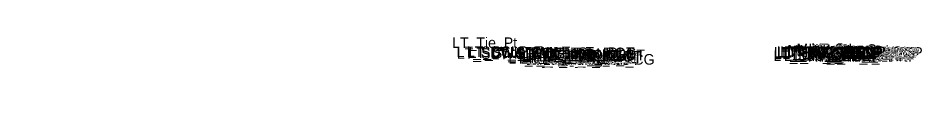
# Model space of a CAD drawing. Extents: x 0 to 4229, y -1 to 9523.
# Drawn here: x 3000 to 3171.5, y 4000 to 4008.4 of the extents above; entities that cross this region are included whole.
import ezdxf

# ---------------------------------------------------------------- set-up
doc = ezdxf.new("R2010")
doc.units = 0
doc.layers.add('Default', color=7, linetype='Continuous')

msp = doc.modelspace()

# ---------------------------------------------------------------- texts
at = {"layer": 'Default'}
for s, height, p in [('LT_Tie_Pt', 2, (3082.37, 4006.27)), ('LT_SDWK_Out_Top', 2, (3083.24, 4004.55)), ('LT_SDWK_Out_Bot', 2, (3083.27, 4004.22)), ('LT_CSLP_Pnt', 2, (3085.17, 4004.58)), ('LT_Sub_Trench_Out_DLT', 2, (3085.49, 4004.38)), ('LT_SDWK_In_Top', 2, (3089.86, 4004.45)), ('LT_SDWK_In_Bot', 2, (3089.89, 4004.12)), ('LT_CG_Top_Face', 2, (3094.76, 4004.34)), ('LT_CG_Top_BOC', 2, (3095.28, 4004.34)), ('LT_CG_Top_Gut', 2, (3095.74, 4003.84)), ('LT_PV2_OEOT', 2, (3099.67, 4003.71)), ('LT_PV1_OEOT', 2, (3100.24, 4003.96)), ('LT_Sub_OEEOP', 2, (3143.35, 4003.81)), ('LT_PV2_OEEOP', 2, (3143.44, 4004.44)), ('LT_PV3_OEEOP', 2, (3143.44, 4004.19)), ('LT_PV1_OEEOP', 2, (3144.01, 4004.56)), ('LT_PV2_IEEOP', 2, (3144.09, 4004.44)), ('LT_PV1_IEEOP', 2, (3144.66, 4004.56)), ('LT_PV2_PGL1', 2, (3145.02, 4004.44)), ('LT_PV3_PGL1', 2, (3145.02, 4004.19)), ('LT_PV2_PGL', 2, (3145.35, 4004.44)), ('LT_PV4_PGL', 2, (3145.35, 4003.81)), ('LT_PV1_PGL', 2, (3145.92, 4004.69)), ('MI_Face In', 2, (3146.04, 4004.85)), ('MI_Bot In', 2, (3147.02, 4004.69)), ('MI_Top In', 2, (3147.75, 4005.1)), ('RT_Sub_OEEOP', 2, (3149.92, 4003.68)), ('RT_PV2_OEEOP', 2, (3150.01, 4004.3)), ('RT_PV3_OEEOP', 2, (3150.01, 4004.05)), ('MI_Crown', 2, (3150.51, 4005.15)), ('RT_PV1_OEEOP', 2, (3150.58, 4004.43)), ('RT_PV2_IEEOP', 2, (3150.66, 4004.3)), ('MI_Face Out', 2, (3151.01, 4004.72)), ('MI_Top Out', 2, (3151.22, 4004.97)), ('RT_PV1_IEEOP', 2, (3151.22, 4004.43)), ('RT_PV2_PGL1', 2, (3151.58, 4004.3)), ('RT_PV3_PGL1', 2, (3151.58, 4004.05)), ('RT_PV2_PGL', 2, (3151.92, 4004.3)), ('RT_PV4_PGL', 2, (3151.92, 4003.68)), ('MI_Bot Out', 2, (3152.01, 4004.55)), ('RT_PV1_PGL', 2, (3152.48, 4004.55)), ('LT_CG1_Shelf_Out', 2, (3093.05, 4003.31)), ('LT_CG_Bot_BOC', 2, (3095.31, 4003.32)), ('LT_Sub_OEOP', 2, (3096.36, 4003.06)), ('LT_Sub_OEOT_CG', 2, (3096.87, 4003.12)), ('LT_CG_Bot_IE', 2, (3099.41, 4003.37)), ('LT_Sub_OEOT', 2, (3099.58, 4003.08)), ('LT_PV3_OEOT', 2, (3099.67, 4003.46)), ('-', 0.0001, (3000, 4000)), ('-', 0.0001, (3000, 4000)), ('-', 0.0001, (3000, 4000)), ('-', 0.0001, (3000, 4000)), ('-', 0.0001, (3000, 4000)), ('-', 0.0001, (3000, 4000)), ('-', 0.0001, (3000, 4000))]:
    msp.add_text(s, height=height, dxfattribs=at).set_placement(p)

doc.saveas('drawing.dxf')
